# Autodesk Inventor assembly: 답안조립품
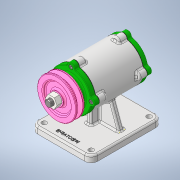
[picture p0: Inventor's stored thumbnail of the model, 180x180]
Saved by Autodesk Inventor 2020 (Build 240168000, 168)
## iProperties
Created: 2022-11
Part Number: 답안조립품
Document SubType Name: Assembly
Designer: owner
Author: owner
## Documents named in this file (12)
- C:\Users\owner\Desktop\721108V1010\답안조립품.iam
- C:\Users\owner\Desktop\721108V1010\본체.ipt
- C:\Users\owner\Desktop\721108V1010\V-벨트풀리.ipt
- C:\Users\owner\Desktop\721108V1010\개스킷.ipt
- C:\Users\owner\Desktop\721108V1010\너트 M12 x 1.25.ipt
- C:\Users\owner\Desktop\721108V1010\뒤커버.ipt
- C:\Users\owner\Desktop\721108V1010\베어링 6204.ipt
- C:\Users\owner\Desktop\721108V1010\볼트 M4 x 12.ipt
- C:\Users\owner\Desktop\721108V1010\앞커버.ipt
- C:\Users\owner\Desktop\721108V1010\오일 실.ipt
- C:\Users\owner\Desktop\721108V1010\축.ipt
- C:\Users\owner\Desktop\721108V1010\키 4 x 4.ipt
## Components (8 placed, 6 different names)
1. V-벨트풀리:1 — 플러쉬:1
2. 개스킷:1
3. KS B 1012 클래스 1 일반 - 미터 M12x1.25:1 — 플러쉬:1
4. KS B 2023 6204 - 20 x 47 x 14:1
5. KS B 2804 D D - 20 32 8:1
6. KS B 1311 (I) 4 x 4 x 12:1
7. KS B 2023 6204 - 20 x 47 x 14:2
8. 개스킷:2
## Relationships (1: Flush 1)
- 플러쉬:1 [Flush]: V-벨트풀리:1 ↔ KS B 1012 클래스 1 일반 - 미터 M12x1.25:1
